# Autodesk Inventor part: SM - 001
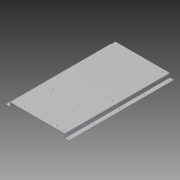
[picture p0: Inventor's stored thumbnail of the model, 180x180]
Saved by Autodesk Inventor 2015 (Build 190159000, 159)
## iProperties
Company: Autodesk, Inc.
Created: 2007-02
Part Number: SM - 001
Material: Steel
Document SubType Name: Sheet Metal
Designer: Autodesk, Inc.
Mass: 11446.2 g
Surface Area: 9666.84 cm^2
Volume: 1458.12 cm^3
Density: 7.85 g/cm^3
Description: Blower Base
Sheet Metal Rule: Default
Appearance: Steel
Author: Autodesk, Inc.
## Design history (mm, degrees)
node "Contour Flange1"
  sketch "Sketch1"
    geometry: L1 (-0.786, 0)-(30.964, 0); L2 (30.964, 0)-(30.964, 31.75); L3 (30.964, 31.75)-(475.464, 31.75); L4 (475.464, 31.75)-(475.464, 0); L5 (475.464, 0)-(507.214, 0)
    constraints: 10 end point, 2 collinear, 2 parallel, 1 horizontal, 1 perpendicular
    dimensions: "d0" = 508 distance of L5.end L1.start; "d1" = 31.75 distance of L1.start L1.end; "d2" = 31.75 distance of L4.end L5.end (= d1); "d3" = 31.75 distance between parallel lines of L5 L3
sketch "Sketch2"
  geometry: 6 further points
hole "Hole1" sketch "Sketch2" at (349.098, -825.747), (399.898, -825.747), (349.098, -424.427), (399.898, -424.427), (349.098, -23.107), (399.898, -23.107) diameter "d13" = 6.7564; stored, may be unused: countersink angle "d17" = 82 deg, drill point angle "d19" = 0 deg; dims "d14" = 12.7, "d15" = 9.525, "d16" = 6.35, "d18" = 19.05
sketch "Sketch3"
  geometry: 2 further points
hole "Hole2" sketch "Sketch3" at (298.425, -30.48), (82.525, -30.48) diameter "d20" = 6.7564; stored, may be unused: countersink angle "d24" = 82 deg, drill point angle "d26" = 0 deg; dims "d21" = 12.7, "d22" = 9.525, "d23" = 6.35, "d25" = 19.05
sketch "Sketch4"
  geometry: 2 further points
hole "Hole3" sketch "Sketch4" at (298.535, -260.35), (82.635, -260.35) diameter "d27" = 6.7564; stored, may be unused: countersink angle "d31" = 82 deg, drill point angle "d33" = 0 deg; dims "d28" = 12.7, "d29" = 9.525, "d30" = 6.35, "d32" = 19.05
hole "Hole4" diameter "d36" = 6.7564; stored, may be unused: countersink angle "d40" = 82 deg, drill point angle "d42" = 118 deg; dims "d34" = 19.05, "d35" = 15.875, "d37" = 12.7, "d38" = 11.1252, "d39" = 6.35, "d41" = 3.048 (= Thickness)
pattern_linear "Rectangular Pattern1" dims "d45" = 203.2, "d48" = 476.25
body "Solid1"
face "Plate1" dims "d4" = 3.048 (= BendReliefWidth), "d5" = 1.524 (= BendReliefDepth), "d6" = 6.096 (= MinimumRemnant), "d7" = 3.048 (= BendRadius), "d8" = 850, "d9" = 3.048 (= BendRadius), "d10" = 3.048, "d11" = 12.192 (= CornerReliefSize), "d12" = 3.048 (= Thickness), "d49" = 3.048 (= JacobiRadiusSize), "SeamGap" = 0.00508, "Thickness" = 3.048
bend "Bend1" dims "d4" = 3.048 (= BendReliefWidth), "d5" = 1.524 (= BendReliefDepth), "d6" = 6.096 (= MinimumRemnant), "d7" = 3.048 (= BendRadius), "d9" = 3.048 (= BendRadius), "d10" = 3.048, "SeamGap" = 0.00508, "Thickness" = 3.048
feature "Corner1" dims "d10" = 3.048, "d11" = 12.192 (= CornerReliefSize), "d12" = 3.048 (= Thickness), "d49" = 3.048 (= JacobiRadiusSize)
other parameters: "BendRadius" = 3.048 (= Thickness), "BendReliefWidth" = 3.048 (= Thickness), "BendReliefDepth" = 1.524 (= 0.5 x Thickness), "CornerReliefSize" = 12.192 (= 4 x Thickness), "MinimumRemnant" = 6.096 (= 2 x Thickness), "TransitionRadius" = 3.048 (= BendRadius), "JacobiRadiusSize" = 3.048 (= Thickness), "GapSize" = 3.048 (= Thickness)
